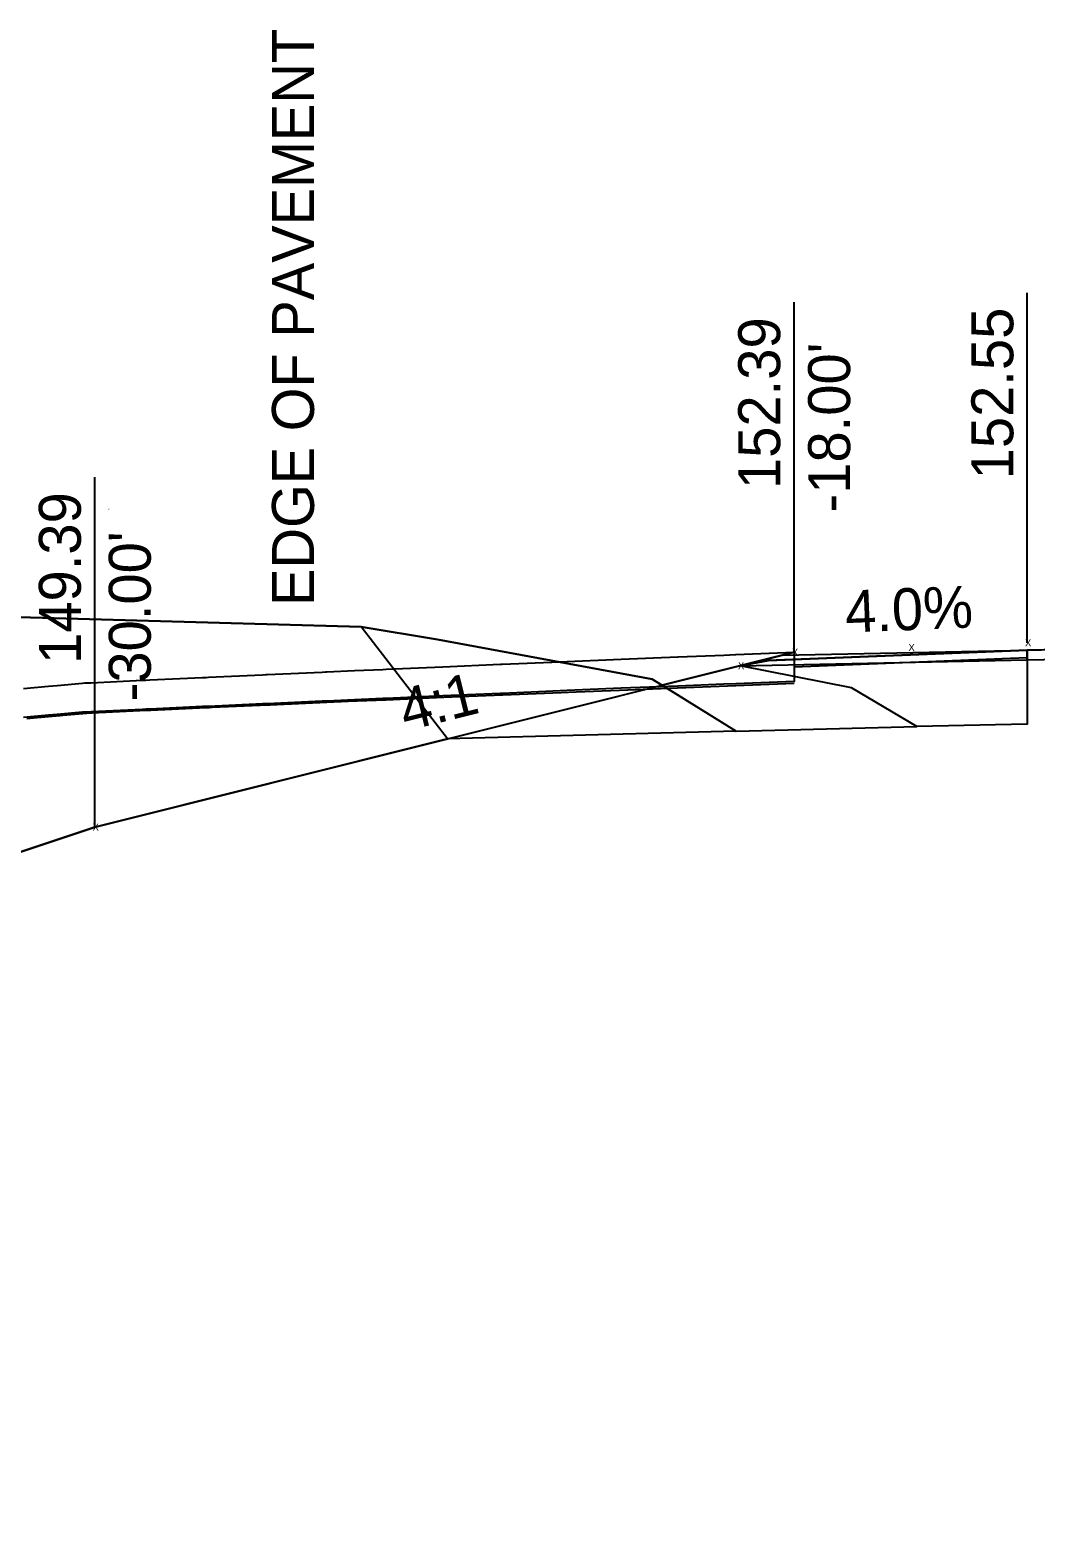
# Model space of a CAD drawing. Extents: x -100 to 4303, y -13 to 10775.
# Drawn here: x 3118.89 to 3136.15, y 5512.2 to 5538.06 of the extents above; entities that cross this region are included whole.
import ezdxf

# ---------------------------------------------------------------- set-up
doc = ezdxf.new("R2010")
doc.units = 0
for name, color, linetype in [('_CIVIL_CONSTRUCTION', 7, 'Continuous'), ('CONST_LV3', 7, 'Continuous'), ('CONST_PROF_LV1', 7, 'Continuous'), ('Default', 7, 'Continuous'), ('DTM CONTOURS_MAJOR', 7, 'Continuous'), ('DTM_P_FINISHED_GRADE', 7, 'Continuous'), ('DTM_TEMP_DROP', 7, 'Continuous'), ('DTM_X_BOUNDARY', 7, 'Continuous'), ('DTM_X_GROUND', 7, 'Continuous'), ('XS_M_SHAPES_EARTHWORK', 7, 'Continuous'), ('XS_P_CRUSHED_STONE', 7, 'Continuous'), ('XS_P_DR_ASPHALT_B', 7, 'Continuous'), ('XS_P_DR_GRAVEL', 7, 'Continuous'), ('XS_P_GROUND', 7, 'Continuous'), ('XS_P_TX_CLEARZONE', 7, 'Continuous'), ('XS_P_TX_FS_BS', 7, 'Continuous'), ('XS_X_EXCESS', 7, 'Continuous')]:
    doc.layers.add(name, color=color, linetype=linetype)

msp = doc.modelspace()

# ---------------------------------------------------------------- linework, layer by layer
at = {"layer": 'CONST_LV3'}
msp.add_lwpolyline([(3120, 5524.389), (3120, 5524.389), (3126.28, 5525.958)], dxfattribs=at)
at = {"layer": 'Default'}
msp.add_lwpolyline([(3150, 5527.704), (3136, 5527.424), (3136, 5527.424), (3136, 5527.257), (3150, 5527.537), (3150, 5527.537), (3150, 5527.704), (3150, 5527.704), (3150, 5527.704)], dxfattribs=at)
at = {"layer": 'DTM_P_FINISHED_GRADE'}
for points in [[(3118.776, 5526.767), (3119.206, 5526.806), (3119.355, 5526.818), (3119.787, 5526.858), (3119.829, 5526.861), (3119.864, 5526.862), (3119.938, 5526.866), (3120.819, 5526.907), (3120.873, 5526.91), (3120.942, 5526.912), (3121.849, 5526.955), (3121.908, 5526.957), (3121.948, 5526.959), (3122.877, 5527.002), (3122.936, 5527.004), (3122.955, 5527.005), (3123.903, 5527.048), (3123.958, 5527.05), (3123.963, 5527.05), (3123.979, 5527.051), (3124.455, 5527.072), (3124.94, 5527.094), (3125.001, 5527.097), (3125.971, 5527.139), (3126.963, 5527.182), (3126.988, 5527.183), (3127.984, 5527.225), (3128.103, 5527.232), (3129.032, 5527.269), (3130.004, 5527.309), (3130.011, 5527.309), (3130.791, 5527.34), (3131, 5527.349), (3132, 5527.389)], [(3118.776, 5526.767), (3119.206, 5526.806), (3119.355, 5526.818), (3119.787, 5526.858), (3119.829, 5526.861), (3119.864, 5526.862), (3119.938, 5526.866), (3120.819, 5526.907), (3120.873, 5526.91), (3120.942, 5526.912), (3121.849, 5526.955), (3121.908, 5526.957), (3121.948, 5526.959), (3122.877, 5527.002), (3122.936, 5527.004), (3122.955, 5527.005), (3123.903, 5527.048), (3123.958, 5527.05), (3123.963, 5527.05), (3123.979, 5527.051), (3124.455, 5527.072), (3124.94, 5527.094), (3125.001, 5527.097), (3125.971, 5527.139), (3126.963, 5527.182), (3126.988, 5527.183), (3127.984, 5527.225), (3128.103, 5527.232), (3129.032, 5527.269), (3130.004, 5527.309), (3130.011, 5527.309), (3130.791, 5527.34), (3131, 5527.349), (3132, 5527.389)], [(3118.835, 5526.253), (3118.893, 5526.258), (3118.945, 5526.262), (3119.4, 5526.303), (3119.449, 5526.307), (3119.908, 5526.349), (3119.924, 5526.35), (3119.952, 5526.351), (3120.891, 5526.394), (3120.949, 5526.397), (3120.959, 5526.397), (3121.917, 5526.44), (3121.967, 5526.442), (3122.016, 5526.444), (3122.975, 5526.487), (3122.981, 5526.487), (3123.007, 5526.488), (3123.98, 5526.53), (3124.475, 5526.552), (3124.503, 5526.553), (3124.996, 5526.574), (3125.991, 5526.616), (3126.995, 5526.657), (3126.998, 5526.657), (3128, 5526.698), (3128.001, 5526.698), (3128.259, 5526.708), (3129, 5526.738), (3130, 5526.778), (3131, 5526.818), (3132, 5526.858)]]:
    msp.add_lwpolyline(points, dxfattribs=at)
at = {"layer": 'DTM_X_GROUND'}
for p, q in [((3126.052, 5525.901), (3124.572, 5527.826)), ((3136, 5527.424), (3150, 5527.704)), ((3136, 5527.424), (3131.405, 5527.24))]:
    msp.add_line(p, q, dxfattribs=at)
for points in [[(3000, 5512.2), (3044.132, 5513.453), (3046.486, 5513.62), (3053.808, 5513.95), (3070.909, 5514.966), (3077.153, 5518.209), (3097.118, 5527.209), (3098.789, 5527.5), (3101.713, 5527.882), (3110.312, 5528.066), (3113.777, 5528.123), (3116.864, 5528.039), (3124.572, 5527.826)], [(3126.052, 5525.901), (3131.405, 5527.24)]]:
    msp.add_lwpolyline(points, dxfattribs=at)
at = {"layer": 'XS_M_SHAPES_EARTHWORK'}
for points in [[(3070.973, 5514.999), (3077.153, 5518.209), (3097.118, 5527.209), (3098.789, 5527.5), (3101.713, 5527.882), (3110.312, 5528.066), (3113.777, 5528.123), (3116.864, 5528.039), (3124.572, 5527.826), (3125.877, 5527.605), (3129.562, 5526.928), (3131.005, 5526.033), (3126.052, 5525.901), (3120, 5524.389), (3093.161, 5515.443)], [(3131.557, 5527.246), (3136, 5527.424), (3136, 5526.153), (3134.107, 5526.115), (3132.985, 5526.777), (3131.075, 5527.157)], [(3131.005, 5526.033), (3134.107, 5526.115), (3132.985, 5526.777), (3131.075, 5527.157), (3132, 5527.389), (3129.734, 5526.822)]]:
    msp.add_lwpolyline(points, close=True, dxfattribs=at)
at = {"layer": 'XS_P_CRUSHED_STONE'}
for p, q in [((3131.8, 5527.339), (3136, 5527.424)), ((3134, 5527.469), (3134, 5527.469)), ((3136, 5527.549), (3136, 5527.549)), ((3136, 5527.549), (3136, 5527.549)), ((3136, 5527.257), (3136, 5527.424)), ((3131.8, 5527.339), (3131.075, 5527.157)), ((3131.075, 5527.157), (3136, 5527.257)), ((3132, 5527.389), (3132, 5527.389)), ((3136, 5527.257), (3136, 5527.257))]:
    msp.add_line(p, q, dxfattribs=at)
at = {"layer": 'XS_P_DR_ASPHALT_B'}
msp.add_lwpolyline([(3132, 5527.264), (3132, 5527.139), (3133, 5527.179), (3133, 5527.179), (3133, 5527.179), (3133, 5527.179), (3134, 5527.219), (3134, 5527.219), (3134, 5527.219), (3134, 5527.219), (3135, 5527.259), (3135, 5527.259), (3135, 5527.259), (3136, 5527.299), (3136, 5527.424), (3135, 5527.384), (3135, 5527.384), (3135, 5527.384), (3134, 5527.344), (3134, 5527.344), (3134, 5527.344), (3134, 5527.344), (3133, 5527.304), (3133, 5527.304), (3133, 5527.304), (3133, 5527.304), (3132, 5527.264)], dxfattribs=at)
at = {"layer": 'XS_P_DR_GRAVEL'}
msp.add_lwpolyline([(3118.776, 5526.767), (3119.206, 5526.806), (3119.355, 5526.818), (3119.787, 5526.858), (3119.829, 5526.861), (3119.864, 5526.862), (3119.938, 5526.866), (3120.819, 5526.907), (3120.873, 5526.91), (3120.942, 5526.912), (3121.849, 5526.955), (3121.908, 5526.957), (3121.948, 5526.959), (3122.877, 5527.002), (3122.936, 5527.004), (3122.955, 5527.005), (3123.903, 5527.048), (3123.958, 5527.05), (3123.963, 5527.05), (3123.979, 5527.051), (3124.455, 5527.072), (3124.94, 5527.094), (3125.001, 5527.097), (3125.971, 5527.139), (3126.963, 5527.182), (3126.988, 5527.183), (3127.984, 5527.225), (3128.103, 5527.232), (3129.032, 5527.269), (3130.004, 5527.309), (3130.011, 5527.309), (3130.791, 5527.34), (3131, 5527.349), (3131, 5527.349), (3131, 5527.349), (3131, 5527.349), (3132, 5527.389), (3132, 5527.389), (3132, 5526.889), (3132, 5526.889), (3131, 5526.849), (3131, 5526.849), (3131, 5526.849), (3131, 5526.849), (3130.791, 5526.84), (3130.011, 5526.809), (3130.004, 5526.809), (3129.032, 5526.769), (3128.103, 5526.732), (3127.984, 5526.725), (3126.988, 5526.683), (3126.963, 5526.682), (3125.971, 5526.639), (3125.001, 5526.597), (3124.94, 5526.594), (3124.455, 5526.572), (3123.979, 5526.551), (3123.963, 5526.55), (3123.958, 5526.55), (3123.903, 5526.548), (3122.955, 5526.505), (3122.936, 5526.504), (3122.877, 5526.502), (3121.948, 5526.459), (3121.908, 5526.457), (3121.849, 5526.455), (3120.942, 5526.412), (3120.873, 5526.41), (3120.819, 5526.407), (3119.938, 5526.366), (3119.864, 5526.362), (3119.829, 5526.361), (3119.787, 5526.358), (3119.355, 5526.318), (3119.206, 5526.306), (3118.776, 5526.267)], dxfattribs=at)
msp.add_lwpolyline([(3118.776, 5526.767), (3119.206, 5526.806), (3119.355, 5526.818), (3119.787, 5526.858), (3119.829, 5526.861), (3119.864, 5526.862), (3119.938, 5526.866), (3120.819, 5526.907), (3120.873, 5526.91), (3120.942, 5526.912), (3121.849, 5526.955), (3121.908, 5526.957), (3121.948, 5526.959), (3122.877, 5527.002), (3122.936, 5527.004), (3122.955, 5527.005), (3123.903, 5527.048), (3123.958, 5527.05), (3123.963, 5527.05), (3123.979, 5527.051), (3124.455, 5527.072), (3124.94, 5527.094), (3125.001, 5527.097), (3125.971, 5527.139), (3126.963, 5527.182), (3126.988, 5527.183), (3127.984, 5527.225), (3128.103, 5527.232), (3129.032, 5527.269), (3130.004, 5527.309), (3130.011, 5527.309), (3130.791, 5527.34), (3131, 5527.349), (3131, 5527.349), (3131, 5527.349), (3131, 5527.349), (3132, 5527.389), (3132, 5527.389), (3132, 5526.889), (3132, 5526.889), (3131, 5526.849), (3131, 5526.849), (3131, 5526.849), (3131, 5526.849), (3130.791, 5526.84), (3130.011, 5526.809), (3130.004, 5526.809), (3129.032, 5526.769), (3128.103, 5526.732), (3127.984, 5526.725), (3126.988, 5526.683), (3126.963, 5526.682), (3125.971, 5526.639), (3125.001, 5526.597), (3124.94, 5526.594), (3124.455, 5526.572), (3123.979, 5526.551), (3123.963, 5526.55), (3123.958, 5526.55), (3123.903, 5526.548), (3122.955, 5526.505), (3122.936, 5526.504), (3122.877, 5526.502), (3121.948, 5526.459), (3121.908, 5526.457), (3121.849, 5526.455), (3120.942, 5526.412), (3120.873, 5526.41), (3120.819, 5526.407), (3119.938, 5526.366), (3119.864, 5526.362), (3119.829, 5526.361), (3119.787, 5526.358), (3119.355, 5526.318), (3119.206, 5526.306), (3118.776, 5526.267)], dxfattribs=at)
at = {"layer": 'XS_P_GROUND'}
msp.add_lwpolyline([(3093.161, 5515.443), (3120, 5524.389), (3120, 5524.389), (3120, 5524.389), (3132, 5527.389)], dxfattribs=at)
at = {"layer": 'XS_P_TX_CLEARZONE'}
for p, q in [((3132, 5527.389), (3132, 5533.389)), ((3132, 5527.389), (3132, 5533.389)), ((3132, 5527.389), (3132, 5533.389)), ((3136, 5527.549), (3136, 5533.549)), ((3136, 5527.549), (3136, 5533.549)), ((3136, 5527.549), (3136, 5533.549)), ((3120, 5524.389), (3120, 5530.389)), ((3120, 5524.389), (3120, 5530.389))]:
    msp.add_line(p, q, dxfattribs=at)
at = {"layer": 'XS_X_EXCESS'}
for p, q in [((3128, 5526.698), (3128.259, 5526.708)), ((3128.259, 5526.708), (3129, 5526.738)), ((3129, 5526.738), (3129.815, 5526.77)), ((3120.891, 5526.394), (3120.949, 5526.397)), ((3120.949, 5526.397), (3120.959, 5526.397)), ((3123.98, 5526.53), (3124.475, 5526.552)), ((3124.475, 5526.552), (3124.503, 5526.553)), ((3118.945, 5526.262), (3119.4, 5526.303)), ((3119.4, 5526.303), (3119.407, 5526.304))]:
    msp.add_line(p, q, dxfattribs=at)
for points in [[(3129.815, 5526.77), (3129.562, 5526.928), (3125.877, 5527.605), (3124.572, 5527.826), (3116.864, 5528.039), (3113.777, 5528.123), (3110.312, 5528.066), (3101.713, 5527.882), (3098.789, 5527.5), (3097.118, 5527.209), (3080.966, 5519.928)], [(3125.991, 5526.616), (3126.995, 5526.657), (3128, 5526.698)], [(3119.908, 5526.349), (3119.924, 5526.35), (3119.952, 5526.351), (3120.891, 5526.394)], [(3120.959, 5526.397), (3121.917, 5526.44), (3121.967, 5526.442)], [(3121.967, 5526.442), (3122.016, 5526.444), (3122.975, 5526.487)], [(3122.975, 5526.487), (3123.007, 5526.488), (3123.469, 5526.508), (3123.491, 5526.509), (3123.98, 5526.53)], [(3124.503, 5526.553), (3124.974, 5526.573), (3124.996, 5526.574), (3125.991, 5526.616)], [(3118.835, 5526.253), (3118.893, 5526.258), (3118.945, 5526.262)], [(3119.407, 5526.304), (3119.449, 5526.308), (3119.864, 5526.345), (3119.908, 5526.349)]]:
    msp.add_lwpolyline(points, dxfattribs=at)

# ---------------------------------------------------------------- texts
at = {"layer": '_CIVIL_CONSTRUCTION'}
for height, p in [(0.12, (3133.961, 5527.409)), (0.12, (3133.961, 5527.409)), (0.001, (3134, 5527.434)), (0.001, (3136, 5527.514)), (0.12, (3131.036, 5527.097)), (0.12, (3131.036, 5527.097))]:
    msp.add_text('X', height=height, dxfattribs=at).set_placement(p)
at = {"layer": 'CONST_PROF_LV1'}
msp.add_text('X', height=0.12, dxfattribs=at).set_placement((3119.961, 5524.329))
at = {"layer": 'Default'}
msp.add_text('X', height=0.12, dxfattribs=at).set_placement((3119.961, 5524.329))
at = {"layer": 'DTM CONTOURS_MAJOR'}
msp.add_text('X', height=0.12, dxfattribs=at).set_placement((3135.961, 5527.489))
msp.add_text('X', height=0.12, dxfattribs=at).set_placement((3135.961, 5527.489))
at = {"layer": 'DTM_TEMP_DROP'}
for height, p in [(0.12, (3131.961, 5527.329)), (0.12, (3131.961, 5527.329)), (0.001, (3132, 5527.354))]:
    msp.add_text('X', height=height, dxfattribs=at).set_placement(p)
at = {"layer": 'DTM_X_BOUNDARY'}
for height, p in [(0.12, (3131.961, 5527.329)), (0.12, (3131.961, 5527.329)), (0.001, (3132, 5526.857))]:
    msp.add_text('X', height=height, dxfattribs=at).set_placement(p)
at = {"layer": 'XS_P_TX_CLEARZONE'}
for s, height, p in [('EDGE OF PAVEMENT', 0.72, (3123.76, 5528.182)), ('152.39', 0.72, (3131.76, 5530.187)), ('152.39', 0.72, (3131.76, 5530.187)), ('152.39', 0.72, (3131.76, 5530.187)), ('152.55', 0.72, (3135.76, 5530.353)), ('152.55', 0.72, (3135.76, 5530.353)), ('152.55', 0.72, (3135.76, 5530.353)), ("-18.00'", 0.72, (3132.96, 5529.785)), ("-18.00'", 0.72, (3132.96, 5529.785)), ("-18.00'", 0.72, (3132.96, 5529.785)), ('149.39', 0.72, (3119.76, 5527.187)), ('149.39', 0.72, (3119.76, 5527.187)), ('149.39', 0.72, (3119.76, 5527.187)), ('149.39', 0.72, (3119.76, 5527.187)), ('148.86', 0.006, (3119.76, 5529.831)), ('148.86', 0.006, (3119.76, 5529.831)), ('148.86', 0.006, (3119.76, 5529.831)), ('148.86', 0.006, (3119.76, 5529.831)), ('148.86', 0.006, (3119.76, 5529.831)), ('148.86', 0.006, (3119.76, 5529.831)), ("-30.00'", 0.006, (3120.246, 5529.826)), ("-30.00'", 0.006, (3120.246, 5529.826)), ("-30.00'", 0.006, (3120.246, 5529.826)), ("-30.00'", 0.006, (3120.246, 5529.826)), ("-30.00'", 0.006, (3120.246, 5529.826)), ("-30.00'", 0.006, (3120.246, 5529.826)), ("-30.00'", 0.72, (3120.96, 5526.546)), ("-30.00'", 0.72, (3120.96, 5526.546)), ("-30.00'", 0.72, (3120.96, 5526.546)), ("-30.00'", 0.72, (3120.96, 5526.546))]:
    msp.add_text(s, height=height, rotation=90, dxfattribs=at).set_placement(p)
at = {"layer": 'XS_P_TX_FS_BS'}
for s, rotation, p in [('4.0%', 2.2906, (3132.887, 5527.724)), ('4:1', 14.0362, (3125.333, 5526.031)), ('4:1', 14.0362, (3125.333, 5526.031))]:
    msp.add_text(s, height=0.72, rotation=rotation, dxfattribs=at).set_placement(p)

doc.saveas('drawing.dxf')
